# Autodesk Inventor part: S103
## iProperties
Author: Administrator
Revision Number: A
Shininess: 41.0
PropertySet Name: _Private Model Information
Created: 2000-11
Part Number: S103
Project: ACME
Description: SCREW, CLAMP
Document SubType Name: Modeling
Designer: E. MOSS
Control State: 0
Master: False
Checked Out: False
PropertySet Name: Design Tracking Control
Density: 0.0
Volumn: 0.0
Area: 0.0
PropertySet Name: Model Information
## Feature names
1. Extrusion1
2. Extrusion2
3. Extrusion3
4. Chamfer1
